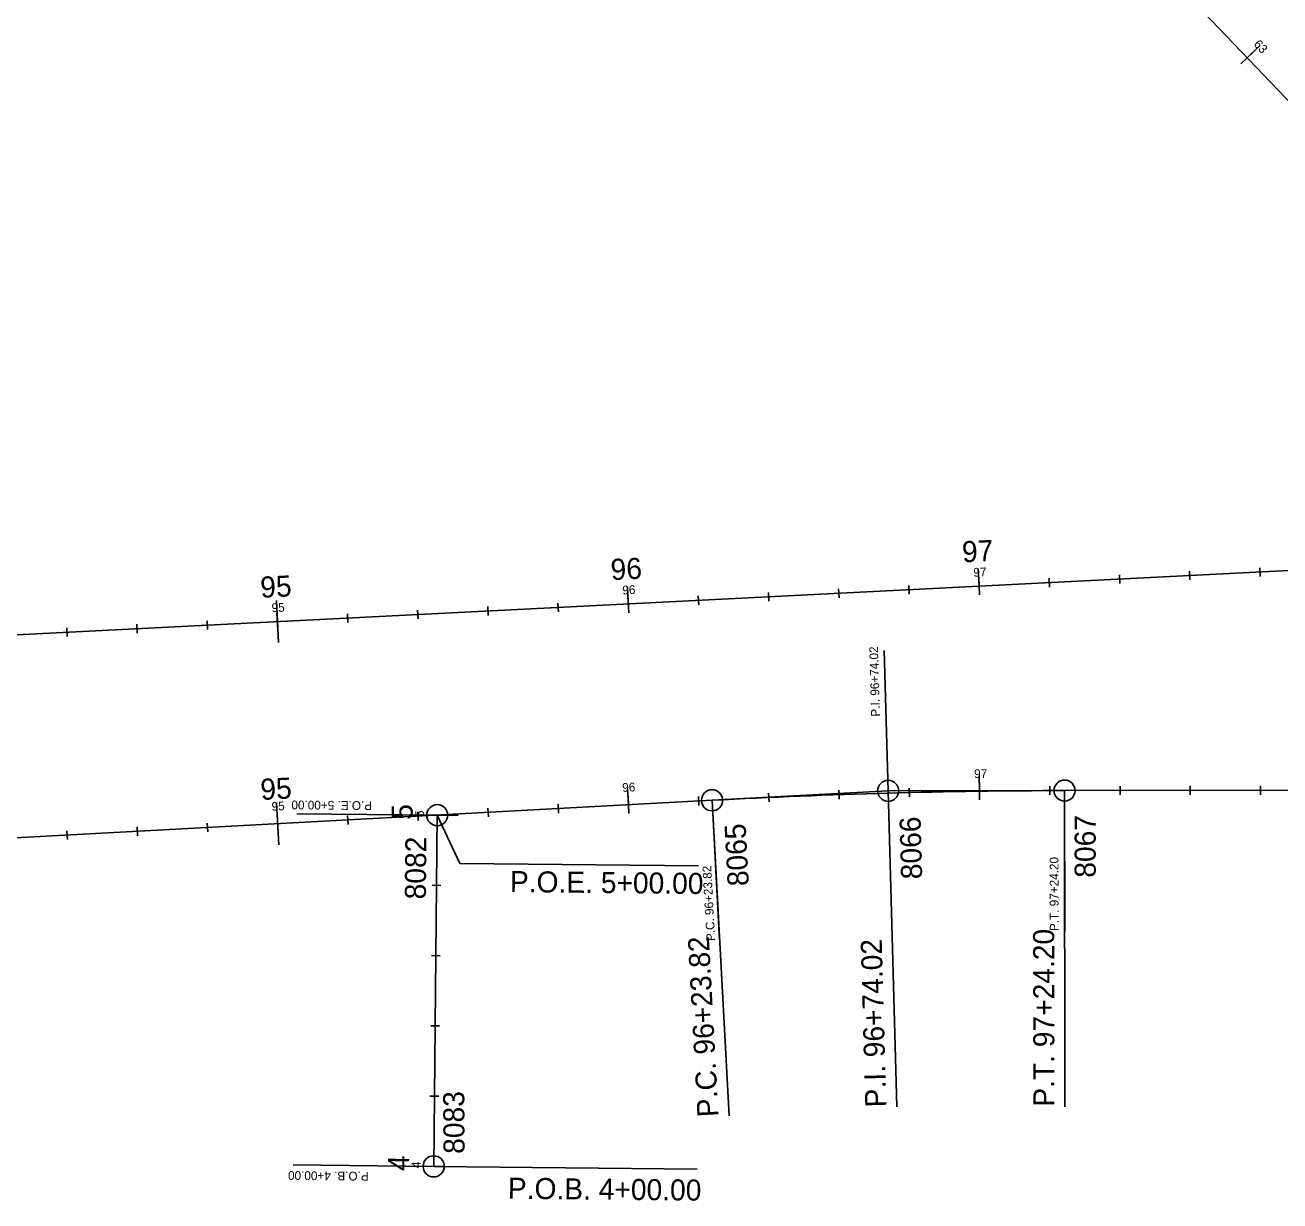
# Model space of a CAD drawing. Extents: x 1708585 to 1714116, y 541444 to 545437.
# Drawn here: x 1711437.5 to 1711794.7, y 544113 to 544447.8 of the extents above; entities that cross this region are included whole.
import ezdxf

# ---------------------------------------------------------------- set-up
doc = ezdxf.new("R2010")
doc.units = 0
for name, color, linetype in [('CL_Highway_1', 7, 'Continuous'), ('CL_Highway_1_40_Sta', 7, 'Continuous'), ('CL_Highway_1_Sta', 7, 'Continuous'), ('CL_Highway_1_Sta_Minor_Text', 7, 'Continuous'), ('CL_Highway_2', 7, 'Continuous'), ('CL_Highway_2_40_Sta', 7, 'Continuous'), ('CL_Highway_2_Sta', 7, 'Continuous'), ('CL_XS_1', 7, 'Continuous'), ('CL_XS_1_40_PText', 7, 'Continuous'), ('CL_XS_1_40_Sta', 7, 'Continuous'), ('CL_XS_1_PText', 7, 'Continuous'), ('CL_XS_1_Sta', 7, 'Continuous'), ('CL_XS_1_Tangent', 7, 'Continuous'), ('CL_XS_2', 7, 'Continuous'), ('CL_XS_2_40_PText', 7, 'Continuous'), ('CL_XS_2_40_Sta', 7, 'Continuous'), ('CL_XS_2_PText', 7, 'Continuous'), ('CL_XS_2_Sta', 7, 'Continuous'), ('Point_CL_XS_1', 7, 'Continuous'), ('Point_CL_XS_2', 7, 'Continuous'), ('Point_Number', 7, 'Continuous')]:
    doc.layers.add(name, color=color, linetype=linetype)

msp = doc.modelspace()

# ---------------------------------------------------------------- linework, layer by layer
at = {"layer": 'CL_Highway_1'}
msp.add_line((1711164.22, 544260.55), (1712107.9, 544308.18), dxfattribs=at)
at = {"layer": 'CL_Highway_1_40_Sta'}
for points in [[(1711768.95, 544292.32), (1711769.07, 544289.83)], [(1711788.92, 544293.33), (1711789.05, 544290.84)], [(1711708.96, 544290.55), (1711709.21, 544285.55)], [(1711729, 544290.31), (1711729.12, 544287.81)], [(1711748.97, 544291.32), (1711749.1, 544288.82)], [(1711609.09, 544285.51), (1711609.34, 544280.51)], [(1711629.12, 544285.27), (1711629.25, 544282.77)], [(1711649.1, 544286.27), (1711649.23, 544283.78)], [(1711669.07, 544287.28), (1711669.2, 544284.79)], [(1711689.05, 544288.29), (1711689.17, 544285.79)], [(1711569.2, 544282.24), (1711569.33, 544279.74)], [(1711589.18, 544283.25), (1711589.3, 544280.75)], [(1711489.3, 544278.21), (1711489.43, 544275.71)], [(1711509.21, 544280.47), (1711509.47, 544275.47)], [(1711529.25, 544280.22), (1711529.38, 544277.73)], [(1711549.23, 544281.23), (1711549.35, 544278.74)], [(1711449.35, 544276.19), (1711449.48, 544273.7)], [(1711469.33, 544277.2), (1711469.45, 544274.7)]]:
    msp.add_lwpolyline(points, dxfattribs=at)
at = {"layer": 'CL_Highway_1_Sta'}
for points in [[(1711708.83, 544293.04), (1711709.09, 544288.05)], [(1711608.96, 544288), (1711609.21, 544283.01)], [(1711509.04, 544283.96), (1711509.64, 544271.98)]]:
    msp.add_lwpolyline(points, dxfattribs=at)
at = {"layer": 'CL_Highway_2'}
msp.add_line((1710887.1, 545378.25), (1711975.18, 544239.94), dxfattribs=at)
at = {"layer": 'CL_Highway_2_40_Sta'}
msp.add_lwpolyline([(1711787.18, 544440.24), (1711783.56, 544436.78)], dxfattribs=at)
at = {"layer": 'CL_Highway_2_Sta'}
msp.add_lwpolyline([(1711788.62, 544441.62), (1711785.37, 544438.51)], dxfattribs=at)
at = {"layer": 'CL_XS_1'}
for p, q in [((1711733.37, 544229.87), (1711982.94, 544230.22)), ((1711341.12, 544211.33), (1711633.04, 544227.1))]:
    msp.add_line(p, q, dxfattribs=at)
msp.add_arc((1711736.01, 542320.01), 1909.86, 90.07938, 93.09078, dxfattribs=at)
at = {"layer": 'CL_XS_1_40_PText'}
for points in [[(1711683.17, 544229.8), (1711682.06, 544269.79)], [(1711733.37, 544229.87), (1711733.42, 544189.87)], [(1711633.04, 544227.1), (1711635.2, 544187.15)]]:
    msp.add_lwpolyline(points, dxfattribs=at)
at = {"layer": 'CL_XS_1_40_Sta'}
for points in [[(1711709.14, 544232.18), (1711709.21, 544227.19)], [(1711609.12, 544228.31), (1711609.39, 544223.31)], [(1711629.16, 544228.14), (1711629.29, 544225.64)], [(1711649.14, 544229.15), (1711649.26, 544226.65)], [(1711669.14, 544229.95), (1711669.23, 544227.45)], [(1711689.15, 544230.55), (1711689.21, 544228.05)], [(1711729.17, 544231.11), (1711729.18, 544228.61)], [(1711749.17, 544231.14), (1711749.17, 544228.64)], [(1711769.17, 544231.17), (1711769.17, 544228.67)], [(1711789.17, 544231.2), (1711789.17, 544228.7)], [(1711569.25, 544224.9), (1711569.38, 544222.41)], [(1711589.22, 544225.98), (1711589.35, 544223.48)], [(1711509.27, 544222.92), (1711509.54, 544217.92)], [(1711529.31, 544222.75), (1711529.44, 544220.25)], [(1711549.28, 544223.82), (1711549.41, 544221.33)], [(1711449.42, 544218.43), (1711449.56, 544215.94)], [(1711469.39, 544219.51), (1711469.53, 544217.01)], [(1711489.36, 544220.59), (1711489.5, 544218.09)]]:
    msp.add_lwpolyline(points, dxfattribs=at)
at = {"layer": 'CL_XS_1_PText'}
for points in [[(1711683.17, 544229.8), (1711685.66, 544139.84)], [(1711733.37, 544229.87), (1711733.49, 544139.87)], [(1711633.04, 544227.1), (1711637.89, 544137.23)]]:
    msp.add_lwpolyline(points, dxfattribs=at)
at = {"layer": 'CL_XS_1_Sta'}
for points in [[(1711709.11, 544234.18), (1711709.17, 544229.69)], [(1711609.01, 544230.3), (1711609.26, 544225.81)], [(1711509.08, 544226.41), (1711509.73, 544214.43)]]:
    msp.add_lwpolyline(points, dxfattribs=at)
at = {"layer": 'CL_XS_1_Tangent'}
for p, q in [((1711633.04, 544227.1), (1711683.17, 544229.8)), ((1711683.17, 544229.8), (1711733.37, 544229.87))]:
    msp.add_line(p, q, dxfattribs=at)
at = {"layer": 'CL_XS_2'}
msp.add_line((1711553.81, 544122.88), (1711554.82, 544222.87), dxfattribs=at)
at = {"layer": 'CL_XS_2_40_PText'}
for points in [[(1711554.82, 544222.87), (1711514.82, 544223.27)], [(1711553.81, 544122.88), (1711513.82, 544123.28)]]:
    msp.add_lwpolyline(points, dxfattribs=at)
at = {"layer": 'CL_XS_2_40_Sta'}
for points in [[(1711552.32, 544222.9), (1711557.32, 544222.85)], [(1711553.37, 544202.89), (1711555.87, 544202.86)], [(1711553.17, 544182.89), (1711555.67, 544182.86)], [(1711552.97, 544162.89), (1711555.47, 544162.86)], [(1711552.76, 544142.89), (1711555.26, 544142.86)], [(1711551.31, 544122.9), (1711556.31, 544122.85)]]:
    msp.add_lwpolyline(points, dxfattribs=at)
at = {"layer": 'CL_XS_2_PText'}
for points in [[(1711554.82, 544222.87), (1711561.28, 544209.11), (1711629.15, 544208.42)], [(1711553.81, 544122.88), (1711628.81, 544122.12)]]:
    msp.add_lwpolyline(points, dxfattribs=at)
at = {"layer": 'CL_XS_2_Sta'}
for p, q in [((1711548.82, 544222.93), (1711560.82, 544222.81)), ((1711549.31, 544122.92), (1711553.81, 544122.88))]:
    msp.add_line(p, q, dxfattribs=at)
at = {"layer": 'Point_CL_XS_1'}
for centre in [(1711683.17, 544229.8), (1711733.37, 544229.87), (1711633.04, 544227.1)]:
    msp.add_circle(centre, 3, dxfattribs=at)
at = {"layer": 'Point_CL_XS_2'}
for centre in [(1711554.82, 544222.87), (1711553.81, 544122.88)]:
    msp.add_circle(centre, 3, dxfattribs=at)

# ---------------------------------------------------------------- texts
at = {"layer": 'CL_Highway_1_40_Sta'}
for s, p in [('97', (1711707.48, 544290.72)), ('96', (1711607.56, 544285.68)), ('95', (1711507.74, 544280.64))]:
    msp.add_text(s, height=2.5, rotation=2.8897, dxfattribs=at).set_placement(p)
at = {"layer": 'CL_Highway_1_Sta'}
msp.add_text('95', height=6, rotation=2.8897, dxfattribs=at).set_placement((1711504.6, 544284.74))
at = {"layer": 'CL_Highway_1_Sta_Minor_Text'}
for s, p in [('97', (1711704.34, 544294.82)), ('96', (1711604.31, 544289.77))]:
    msp.add_text(s, height=6, rotation=2.8897, dxfattribs=at).set_placement(p)
at = {"layer": 'CL_Highway_2_40_Sta'}
msp.add_text('63', height=2.5, rotation=313.7074, dxfattribs=at).set_placement((1711787.04, 544442.2))
at = {"layer": 'CL_XS_1_40_PText'}
for s, rotation, p in [('P.I. 96+74.02', 91.5851, (1711680.83, 544250.97)), ('P.T. 97+24.20', 90.0794, (1711731.67, 544189.87)), ('P.C. 96+23.82', 93.0908, (1711633.95, 544187.09))]:
    msp.add_text(s, height=2.5, rotation=rotation, dxfattribs=at).set_placement(p)
at = {"layer": 'CL_XS_1_40_Sta'}
for s, rotation, p in [('97', 0.8053, (1711707.66, 544233.41)), ('96', 3.0908, (1711607.54, 544229.47)), ('95', 3.0908, (1711507.74, 544224.09))]:
    msp.add_text(s, height=2.5, rotation=rotation, dxfattribs=at).set_placement(p)
at = {"layer": 'CL_XS_1_PText'}
for s, rotation, p in [('P.T. 97+24.20', 90.0794, (1711730.49, 544139.87)), ('P.C. 96+23.82', 93.0908, (1711634.9, 544137.06)), ('P.I. 96+74.02', 91.5851, (1711682.66, 544139.75))]:
    msp.add_text(s, height=6, rotation=rotation, dxfattribs=at).set_placement(p)
at = {"layer": 'CL_XS_1_Sta'}
msp.add_text('95', height=6, rotation=3.0908, dxfattribs=at).set_placement((1711504.64, 544227.17))
at = {"layer": 'CL_XS_2_40_PText'}
for s, p in [('P.O.E. 5+00.00', (1711536.29, 544226.81)), ('P.O.B. 4+00.00', (1711535.32, 544121.31))]:
    msp.add_text(s, height=2.5, rotation=179.424, dxfattribs=at).set_placement(p)
at = {"layer": 'CL_XS_2_40_Sta'}
for s, p in [('5', (1711551.06, 544222.34)), ('4', (1711550.06, 544122.35))]:
    msp.add_text(s, height=2.5, rotation=89.424, dxfattribs=at).set_placement(p)
at = {"layer": 'CL_XS_2_PText'}
for s, p in [('P.O.E. 5+00.00', (1711575.49, 544200.96)), ('P.O.B. 4+00.00', (1711574.9, 544113.66))]:
    msp.add_text(s, height=6, rotation=359.424, dxfattribs=at).set_placement(p)
at = {"layer": 'CL_XS_2_Sta'}
for s, p in [('5', (1711547.8, 544221.52)), ('4', (1711546.8, 544121.53))]:
    msp.add_text(s, height=6, rotation=89.424, dxfattribs=at).set_placement(p)
at = {"layer": 'Point_Number'}
for s, rotation, p in [('8066', 91.5851, (1711692.87, 544204.7)), ('8067', 90.0794, (1711742.25, 544205.07)), ('8065', 93.0908, (1711643.52, 544202.8)), ('8082', 89.424, (1711551.58, 544198.87)), ('8083', 90.3393, (1711562.61, 544126.46))]:
    msp.add_text(s, height=6, rotation=rotation, dxfattribs=at).set_placement(p)

doc.saveas('drawing.dxf')
